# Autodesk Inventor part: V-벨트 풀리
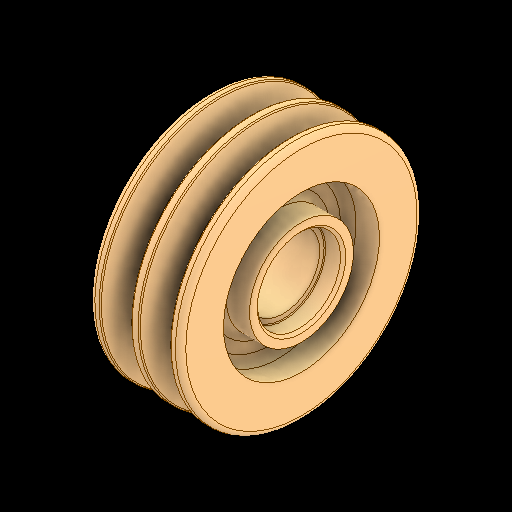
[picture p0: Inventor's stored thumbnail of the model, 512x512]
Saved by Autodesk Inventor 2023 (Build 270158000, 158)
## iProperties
Created: 2025-01
Part Number: V-벨트 풀리
Material: 강철, 주조
Document SubType Name: Modeling
Designer: 강의실01
Density: 7.85 g/cm^3
Appearance: 기본값
Author: jhkim
Sending System: Autodesk Inventor 2025
Preprocessor: ST-DEVELOPER v20
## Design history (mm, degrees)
feature "솔리드1"
node "솔리드2"
